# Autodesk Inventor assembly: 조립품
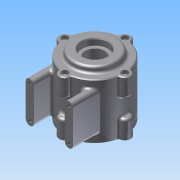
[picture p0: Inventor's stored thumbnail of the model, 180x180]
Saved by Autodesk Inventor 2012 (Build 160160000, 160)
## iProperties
Created: 2007-01
Part Number: 조립품
Document SubType Name: Assembly
Designer: net
Author: net
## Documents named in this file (4)
- C:\Users\net\Desktop\450305V1047\조립품.iam
- C:\Users\net\Desktop\450305V1047\본체.ipt
- C:\Users\net\Desktop\450305V1047\커버2.ipt
- C:\Users\net\Desktop\450305V1047\커버.ipt
